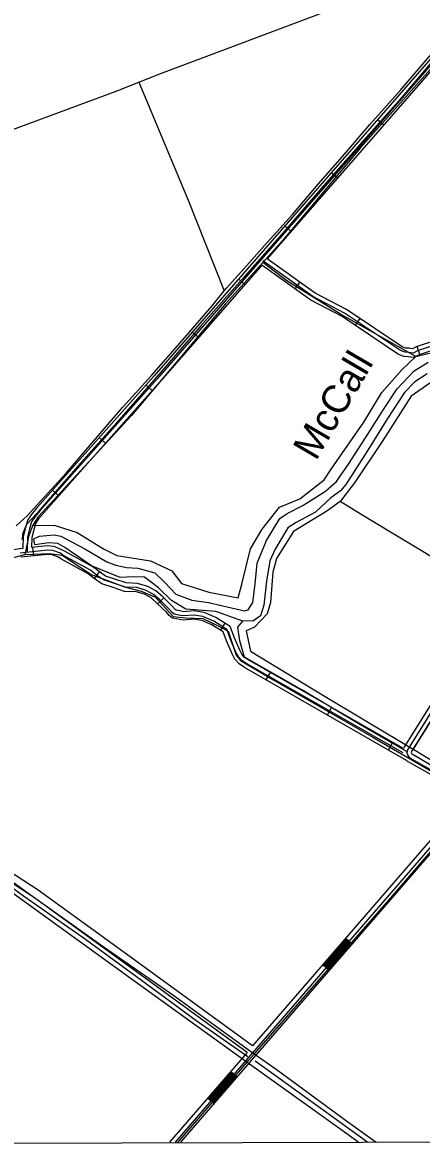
# Model space of a CAD drawing. Extents: x 3361039 to 3398939, y 576572 to 602007.
# Drawn here: x 3372925 to 3374341, y 581957 to 585960 of the extents above; entities that cross this region are included whole.
import ezdxf

# ---------------------------------------------------------------- set-up
doc = ezdxf.new("R2010")
doc.units = 0
for name, color, linetype in [('V-DTCH-CNTR', 7, 'Continuous'), ('V-GRID-FRAM', 7, 'Continuous'), ('V-RIVR-IDEN', 7, 'Continuous'), ('V-ROAD-CNTR', 7, 'Continuous'), ('V-TOPO-SHOR', 7, 'Continuous')]:
    doc.layers.add(name, color=color, linetype=linetype)

msp = doc.modelspace()

# ---------------------------------------------------------------- linework, layer by layer
at = {"layer": 'V-DTCH-CNTR'}
for points in [[(3375784.7, 586089), (3375396, 586200.6), (3375027.9, 586316.6), (3374864.4, 586363.9), (3374599, 586049.7), (3374409, 585835), (3374400.2, 585825.1), (3374123, 585513.5), (3373850.3, 585187.5), (3373777.9, 585107.2), (3373645.3, 584960.2), (3373311.6, 584563.5), (3372980.5, 584203.9), (3372962.1, 584174.3)], [(3371180.1, 584938.3), (3371367.9, 585013.1), (3371856.6, 585194), (3372334.3, 585368.4), (3372740, 585524.6), (3373257.3, 585716.4), (3373338.4, 585748.5), (3373418.4, 585780.2), (3374029.4, 586009.4), (3374678.2, 586257), (3374785.8, 586307.4)], [(3372902.2, 584172.5), (3372942, 584207.5), (3372989.9, 584261.3), (3373079.7, 584359), (3373185.7, 584482.7), (3373280.4, 584592.2), (3373383.5, 584705.7), (3373492.6, 584831.4), (3373597.8, 584954), (3373641, 585006.8), (3373649, 585016.7), (3373710.5, 585084.7), (3373792.9, 585179), (3373882.7, 585277.9), (3373973.9, 585385.4), (3374061, 585483.6), (3374159, 585599.2), (3374265.7, 585718.6), (3374371.6, 585843.2)], [(3373338.4, 585748.5), (3373513.3, 585328.8), (3373641, 585006.8)], [(3374320.8, 584773.9), (3374053.6, 584924.5), (3373862.8, 585042.1), (3373777.9, 585107.2)], [(3372962.1, 584174.3), (3373041.4, 584173), (3373119.3, 584148.5), (3373212.8, 584090.9), (3373260.4, 584066.4), (3373378.8, 584047.4), (3373455.1, 584011.9), (3373489.5, 583967.2), (3373585.8, 583937.1), (3373690.4, 583915.9), (3373703.1, 583964.6), (3373734.1, 584089.9), (3373775.6, 584160.5), (3373837.2, 584238.3), (3373908.9, 584268.4), (3373995, 584335.4), (3374020.8, 584373.4), (3374136.5, 584540), (3374200, 584645.8), (3374270.6, 584725.8), (3374320.8, 584773.9), (3374412.3, 584796.6)], [(3374374.3, 584681), (3374304.7, 584632.8), (3374200.9, 584471.6), (3374103, 584325.1), (3374052.6, 584258.1), (3374005.5, 584224.7), (3373887, 584151.6), (3373826.1, 584056.7), (3373813.9, 584008), (3373805, 583900.4), (3373793.9, 583859.7), (3373748.5, 583812), (3373718.8, 583798.8), (3373733.8, 583726.4), (3373993.3, 583569.7), (3374311.4, 583379.3), (3374313.9, 583377.8), (3374665, 583164.1)], [(3375031.8, 584520.4), (3374983.8, 584461.4), (3374631.6, 583893.4), (3374616, 583868.3), (3374311.4, 583379.3)], [(3374631.6, 583893.4), (3374417.9, 584036.9), (3374133.1, 584209.2), (3374052.6, 584258.1)], [(3372962.1, 584174.3), (3372946.5, 584133.8), (3372942, 584108), (3372933.5, 584070.8)], [(3372794.7, 584033.7), (3372933.5, 584070.8), (3373020.4, 584074.2), (3373065.9, 584068.2), (3373171.1, 583997.6), (3373217.8, 583981.6), (3373286.7, 583955.8), (3373346.3, 583939.6), (3373397.7, 583918.9), (3373459.7, 583849.9), (3373503.3, 583845), (3373565.4, 583843), (3373619.6, 583816.9), (3373654.4, 583798.3), (3373683.9, 583712.8), (3373699.2, 583693.6), (3373819.1, 583623.3), (3374168.6, 583420.9), (3374431, 583269), (3374538.8, 583205.7), (3374768.1, 583071.1), (3375156.5, 582841.1), (3375292, 582766.2), (3375295.2, 582764.1)], [(3374180.4, 581981.9), (3374079.4, 582054.1), (3373825.4, 582241.1), (3373747.2, 582295.4), (3373683.4, 582341.9), (3373461.9, 582502.3), (3373211.8, 582676.9), (3372944, 582866.9), (3372685.9, 583054.1), (3372476.6, 583203.3), (3372256.4, 583359.5), (3372223.3, 583383.8)], [(3372203.3, 583356.7), (3372715.3, 582994.1), (3373293.8, 582575.7), (3373722.7, 582267.3), (3374059.1, 582025.3), (3374119.5, 581981.7)], [(3373475.6, 581979.9), (3373722.7, 582267.3), (3373728.5, 582274), (3373747.2, 582295.4), (3374224.5, 582842.2), (3374538.8, 583205.7)]]:
    msp.add_lwpolyline(points, dxfattribs=at)
at = {"layer": 'V-GRID-FRAM'}
msp.add_lwpolyline([(3365114.8, 600140.3), (3396720.3, 600227.7), (3396778.5, 582044.3), (3365157.1, 581956.9), (3365114.8, 600140.3)], dxfattribs=at)
at = {"layer": 'V-ROAD-CNTR'}
for p, q in [((3374206.7, 585595.3), (3374184.1, 585615)), ((3374042.6, 585406.7), (3374019.9, 585426.4)), ((3373878.4, 585218.1), (3373855.8, 585237.8)), ((3373714.3, 585029.5), (3373691.7, 585049.2)), ((3373892.2, 585013.3), (3373909.7, 585037.7)), ((3374106.1, 584884), (3374122.9, 584908.9)), ((3373550.2, 584841), (3373527.5, 584860.7)), ((3374335, 584780.3), (3374325.5, 584808.8)), ((3373385.6, 584652.5), (3373363.2, 584672.5)), ((3373219.8, 584465.5), (3373197.3, 584485.4)), ((3373053.9, 584278.5), (3373031.4, 584298.4)), ((3372965.3, 584065.5), (3372962.1, 584095.3)), ((3373180.8, 583984.2), (3373197.9, 584008.8)), ((3373405.5, 583894.6), (3373426.5, 583916.1)), ((3373628.2, 583800.8), (3373644.2, 583826.2)), ((3373790.1, 583625), (3373805, 583651.1)), ((3374007.3, 583501.2), (3374022.1, 583527.3)), ((3374224.5, 583377.4), (3374239.3, 583403.4)), ((3374094.9, 582687.3), (3374072.2, 582706.9)), ((3374013.2, 582592.7), (3373990.5, 582612.3)), ((3373686.3, 582214.4), (3373663.6, 582234)), ((3373604.5, 582119.8), (3373581.8, 582139.4))]:
    msp.add_line(p, q, dxfattribs=at)
for points in [[(3376190.1, 586249.6), (3376155.1, 586113.4), (3376145.1, 586086.7), (3376135.6, 586062.2), (3376113.6, 586027.6), (3376089.7, 585987.5), (3375894.5, 585732.4), (3375125.4, 584721.6), (3374962.3, 584451.1), (3374293.7, 583380.5), (3374287.9, 583369.8), (3374292.8, 583355.9), (3374297, 583349.8), (3374498.5, 583235.6), (3374512.8, 583221.9), (3374517.6, 583212.9), (3374516.6, 583202.2), (3374514.4, 583195.6), (3373466.5, 581983)], [(3375416.5, 585128.9), (3374427.8, 585842.3), (3374417.2, 585848.7), (3374401.2, 585851.1), (3374391.3, 585847.7), (3374381.8, 585842.1), (3373392.5, 584705.5), (3372977, 584237), (3372958, 584214.9), (3372943.7, 584193.2), (3372935.9, 584165.9), (3372928.1, 584134.8), (3372926.6, 584091.5)], [(3375409.4, 585115.6), (3374419.5, 585829.8), (3374412, 585834.3), (3374402.7, 585835.7), (3374397.6, 585834), (3374391.5, 585830.4), (3373403.8, 584695.6), (3372988.3, 584227.1), (3372970, 584205.9), (3372957.5, 584186.8), (3372950.4, 584162), (3372943.1, 584132.7), (3372941.2, 584079.5)], [(3375398.3, 585105), (3374411.2, 585817.3), (3374406.8, 585820), (3374404.1, 585820.4), (3374403.8, 585820.3), (3374401.2, 585818.7), (3373793.7, 585120.7)], [(3374397.1, 584832.7), (3374321.7, 584807.5), (3374308.4, 584801.2), (3374297.1, 584802.8), (3374285.8, 584803.5), (3374272.7, 584808.1), (3374075.2, 584941), (3373963.6, 584999.1), (3373793.7, 585120.7)], [(3373773.9, 585098), (3373415.1, 584685.7), (3372999.6, 584217.2), (3372982, 584196.8), (3372971.3, 584180.5), (3372964.9, 584158.1), (3372958, 584130.6), (3372956.7, 584094.7)], [(3374405, 584803.7), (3374332.9, 584779.6), (3374313.1, 584770.2), (3374294.1, 584772.9), (3374279.8, 584773.8), (3374259.1, 584781.1), (3374059.9, 584915.2), (3373947.8, 584973.5), (3373773.9, 585098)], [(3374401.1, 584818.2), (3374327.3, 584793.6), (3374310.8, 584785.7), (3374295.6, 584787.9), (3374282.8, 584788.7), (3374265.9, 584794.6), (3374067.5, 584928.1), (3373955.7, 584986.3), (3373778.2, 585113.4)], [(3375097.7, 584704.8), (3374949.5, 584458.9), (3374280.7, 583388.1), (3374277.3, 583381.8)], [(3375011.8, 584504.2), (3374975, 584443.2), (3374306.7, 583373), (3374304.3, 583368.5), (3374306.3, 583362.7), (3374307.4, 583361.2), (3374507.5, 583247.7), (3374524.9, 583231), (3374532.9, 583216), (3374531.4, 583199.1), (3374527.6, 583188), (3373486.4, 581983.1)], [(3372926.6, 584091.5), (3372915, 584090.3), (3372856.5, 584081.5), (3372823.9, 584073.5), (3372802.2, 584061.9), (3372786.5, 584049.5), (3372779.1, 584041.2)], [(3374275.3, 583365.6), (3373720.7, 583681.9), (3373703.3, 583693.6), (3373691.1, 583707.1), (3373682.3, 583723.5), (3373663.1, 583768.6), (3373649.7, 583805.1), (3373639.2, 583811.6), (3373604.2, 583833.7), (3373565.6, 583850.1), (3373533.3, 583855.2), (3373497, 583852.1), (3373485.9, 583853.8), (3373463.6, 583858.2), (3373456.6, 583864), (3373446.8, 583875.3), (3373412.4, 583908.9), (3373390, 583928.8), (3373363.7, 583942.8), (3373331.1, 583952.8), (3373290.2, 583954.3), (3373251.6, 583967.5), (3373213.1, 583980.1), (3373187.9, 583997.5), (3373166, 584014.2), (3373068.9, 584067.9), (3373059.8, 584074.8), (3373033.4, 584085), (3373013.9, 584085.7), (3372916.9, 584075.4)], [(3374277.3, 583381.8), (3373728.7, 583694.6), (3373713.2, 583705), (3373703.4, 583715.8), (3373695.9, 583730), (3373677, 583774.1), (3373662, 583815.1), (3373647.2, 583824.3), (3373611.2, 583847.1), (3373569.7, 583864.6), (3373533.8, 583870.3), (3373497.6, 583867.2), (3373488.5, 583868.6), (3373470.3, 583872.1), (3373467.2, 583874.7), (3373457.7, 583885.6), (3373422.6, 583919.9), (3373398.6, 583941.2), (3373369.5, 583956.8), (3373333.6, 583967.7), (3373292.9, 583969.2), (3373256.4, 583981.7), (3373219.8, 583993.7), (3373196.7, 584009.7), (3373174.2, 584026.8), (3373077.1, 584080.5), (3373067.6, 584085.6), (3373037, 584098.3), (3373013.4, 584100.7), (3372956.7, 584094.7)], [(3374287.6, 583338.4), (3373712.8, 583669.1), (3373693.4, 583682.2), (3373678.7, 583698.4), (3373668.8, 583717), (3373649.1, 583763.1), (3373637.4, 583795.1), (3373631.3, 583798.9), (3373597.2, 583820.4), (3373561.4, 583835.6), (3373532.7, 583840.1), (3373496.5, 583837), (3373483.4, 583839), (3373456.9, 583844.2), (3373446.1, 583853.3), (3373435.9, 583865), (3373402.1, 583897.9), (3373381.4, 583916.4), (3373358, 583928.9), (3373328.6, 583937.9), (3373287.4, 583939.4), (3373246.9, 583953.3), (3373206.3, 583966.5), (3373179.1, 583985.4), (3373157.7, 584001.6), (3373060.7, 584055.3), (3373052.8, 584060.7), (3373030.5, 584069.4), (3373014.4, 584070.7), (3372918.8, 584060.6)], [(3373741.8, 582324.5), (3373307.8, 582641.2), (3372980.7, 582878.4), (3372851.8, 582961.6), (3372381, 583301.7), (3372252.2, 583402.1)], [(3373722.1, 582301.7), (3373290.1, 582616.9), (3372963.8, 582853.7), (3372834.8, 582936.8), (3372363, 583277.7), (3372234, 583378.3)], [(3374287, 583338.3), (3374489.5, 583223.4), (3374500.7, 583212.7), (3374502.2, 583209.8), (3374501.8, 583205.3), (3374501.1, 583203.2), (3373741.8, 582324.5)], [(3374074.5, 582704.9), (3373992.8, 582610.4)], [(3374076.8, 582703), (3373995, 582608.4)], [(3374079, 582701), (3373997.3, 582606.4)], [(3374081.3, 582699.1), (3373999.6, 582604.5)], [(3374083.6, 582697.1), (3374001.8, 582602.5)], [(3374085.8, 582695.1), (3374004.1, 582600.6)], [(3374088.1, 582693.2), (3374006.4, 582598.6)], [(3374090.4, 582691.2), (3374008.7, 582596.6)], [(3374092.7, 582689.3), (3374010.9, 582594.7)], [(3373722.1, 582301.7), (3373446.7, 581983)], [(3373665.8, 582232), (3373584.1, 582137.5)], [(3373668.1, 582230.1), (3373586.4, 582135.5)], [(3373670.4, 582228.1), (3373588.7, 582133.5)], [(3373672.7, 582226.2), (3373590.9, 582131.6)], [(3373674.9, 582224.2), (3373593.2, 582129.6)], [(3373677.2, 582222.2), (3373595.5, 582127.7)], [(3373679.5, 582220.3), (3373597.7, 582125.7)], [(3373681.7, 582218.3), (3373600, 582123.7)], [(3373684, 582216.4), (3373602.3, 582121.8)]]:
    msp.add_lwpolyline(points, dxfattribs=at)
at = {"layer": 'V-TOPO-SHOR'}
for points in [[(3374846.8, 586397.7), (3374836.1, 586348), (3374804.1, 586302.8), (3374746.2, 586241.2), (3374567.3, 586033.3), (3374476.1, 585928.3), (3374371.5, 585813.3), (3374259.2, 585681), (3374125.2, 585530.2), (3373992.8, 585379.8), (3373846.1, 585209.9), (3373705.5, 585049.7), (3373558.4, 584882.4), (3373416.1, 584717.6), (3373250, 584528.3), (3373131.9, 584396.3), (3373014.9, 584262.6), (3372975.8, 584216.1), (3372939.3, 584177.1), (3372925, 584142.9), (3372924.3, 584122.9)], [(3374361.3, 584711.7), (3374316.7, 584683.5), (3374280, 584646.3), (3374219.9, 584554), (3374150.8, 584440.5), (3374072.6, 584319.5), (3374053.5, 584296.1), (3374019.8, 584271.3), (3373964.6, 584220.2), (3373895.9, 584183.8), (3373866.9, 584165.5), (3373821.4, 584088.9), (3373802.7, 584047.4), (3373790.4, 583975.9), (3373781.8, 583889.9), (3373770.1, 583852.4), (3373744.9, 583834.7), (3373706.6, 583833.5), (3373610.6, 583867.6), (3373505.3, 583875.7), (3373453.3, 583906.5), (3373407.3, 583951.4), (3373358.3, 583989.5), (3373318.9, 583990.8), (3373271.7, 583988.5), (3373169.6, 584029.8), (3373117.2, 584067.3), (3373075.2, 584095.3), (3373050, 584109.7), (3373019, 584111.4), (3372969.2, 584104.4), (3372965.8, 584126.5), (3372985, 584135.9), (3373037.2, 584139.6), (3373060.9, 584135.1), (3373146.8, 584090.8), (3373224.2, 584044.8), (3373255.8, 584032), (3373294.6, 584023.8), (3373334.6, 584022.1), (3373394.9, 584005.2), (3373430.7, 583971.2), (3373468.9, 583929.2), (3373526, 583908.1), (3373585.7, 583899.8), (3373635.6, 583888.3), (3373712.4, 583870.4), (3373725.6, 583873.5), (3373742.4, 583900.3), (3373750.6, 583965.7), (3373758, 584039.4), (3373790.6, 584119.5), (3373838.4, 584198.3), (3373864.4, 584215.9), (3373920.4, 584244.6), (3374000.3, 584295.1), (3374038.8, 584329.6), (3374082.1, 584391.1), (3374141.8, 584485.3), (3374206.4, 584584.9), (3374254.3, 584658.6), (3374314.5, 584723.1), (3374364.6, 584753.4)], [(3374292.4, 583368.5), (3374116.5, 583470.2), (3373916.3, 583589.3), (3373713.3, 583706.1), (3373696.7, 583763.2), (3373688.7, 583812.2), (3373706.6, 583833.5)], [(3373724.3, 582285.6), (3373540.3, 582415.4), (3373347.8, 582557.6), (3373148.2, 582702.2), (3372928.6, 582856.3), (3372716.5, 583010.3), (3372518.8, 583155.6), (3372304.7, 583309.2), (3372235, 583358.3)], [(3375221.8, 582817.4), (3375060, 582913.1), (3374871.9, 583024), (3374692.5, 583129.8), (3374515.5, 583236.7), (3374315.7, 583356.7)], [(3374150.9, 581981.8), (3374004.5, 582087), (3373776, 582252.9), (3373750.4, 582270.9)]]:
    msp.add_lwpolyline(points, dxfattribs=at)

# ---------------------------------------------------------------- texts
at = {"layer": 'V-RIVR-IDEN'}
msp.add_text('McCall', height=100, rotation=59.6206, dxfattribs=at).set_placement((3373966.3, 584400.2))

doc.saveas('drawing.dxf')
